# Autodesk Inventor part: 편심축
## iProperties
Manager: 한국ATC센터
Company: 한국ATC센터
Created: 2014-10
Part Number: 편심축
Document SubType Name: Modeling
Designer: 한국ATC센터
Density: 7.86 g/cm^3
Material: 강, 연강
Mass: 1420.77 g
Surface Area: 286.546 cm^2
Volume: 180.76 cm^3
Author: KYOUNG IL JANG
